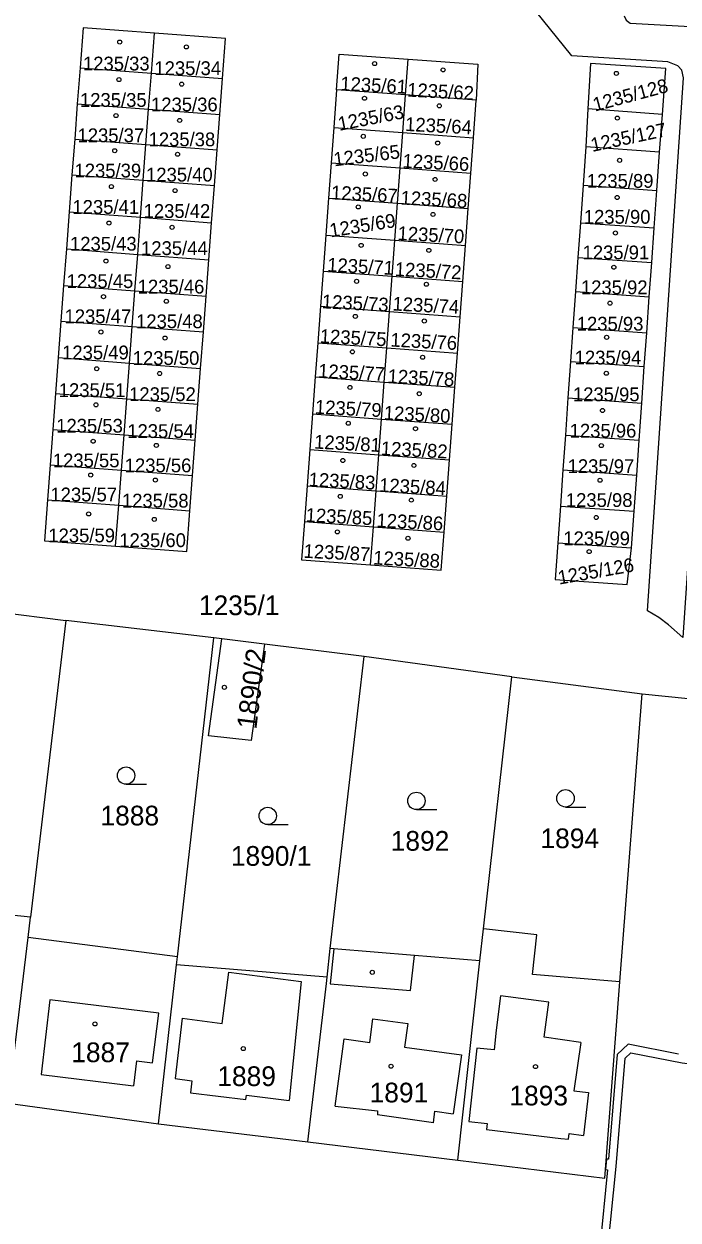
# Model space of a CAD drawing. Extents: x -869103 to -863415, y -1015889 to -1012477.
# Drawn here: x -866138.2 to -866081.7, y -1014098.2 to -1013995 of the extents above; entities that cross this region are included whole.
import ezdxf

# ---------------------------------------------------------------- set-up
doc = ezdxf.new("R2010")
doc.units = 0
for name, color, linetype in [('Hranice parcel', 7, 'Continuous'), ('Parcelní čísla', 7, 'Continuous'), ('Vnitřní kresba', 7, 'Continuous'), ('Věcná břemena k části', 7, 'Continuous'), ('Značky budov', 7, 'Continuous'), ('Značky kultur', 7, 'Continuous')]:
    doc.layers.add(name, color=color, linetype=linetype)

msp = doc.modelspace()

# ---------------------------------------------------------------- linework, layer by layer
at = {"layer": 'Hranice parcel'}
for p, q in [((-866127.17, -1013999.26), (-866126.91, -1013995.83)), ((-866105.24, -1014001.15), (-866105.01, -1013998.06)), ((-866133.32, -1013998.8), (-866133.56, -1014001.93)), ((-866133.32, -1013998.8), (-866127.17, -1013999.26)), ((-866127.41, -1014002.39), (-866127.17, -1013999.26)), ((-866127.17, -1013999.26), (-866121.03, -1013999.72)), ((-866121.27, -1014002.85), (-866121.03, -1013999.72)), ((-866111.2, -1014000.71), (-866111.44, -1014003.96)), ((-866105.24, -1014001.15), (-866111.2, -1014000.71)), ((-866105.48, -1014004.4), (-866105.24, -1014001.15)), ((-866099.15, -1014001.61), (-866105.24, -1014001.15)), ((-866099.39, -1014004.85), (-866099.15, -1014001.61)), ((-866133.56, -1014001.93), (-866133.78, -1014004.96)), ((-866133.56, -1014001.93), (-866127.41, -1014002.39)), ((-866127.64, -1014005.43), (-866127.41, -1014002.39)), ((-866127.41, -1014002.39), (-866121.27, -1014002.85)), ((-866121.5, -1014005.89), (-866121.27, -1014002.85)), ((-866089.51, -1014002.36), (-866089.7, -1014005.63)), ((-866083.08, -1014002.83), (-866089.51, -1014002.36)), ((-866083.33, -1014006.08), (-866083.08, -1014002.83)), ((-866111.44, -1014003.96), (-866111.67, -1014007)), ((-866111.44, -1014003.96), (-866105.48, -1014004.4)), ((-866105.71, -1014007.44), (-866105.48, -1014004.4)), ((-866105.48, -1014004.4), (-866099.39, -1014004.85)), ((-866099.62, -1014007.9), (-866099.39, -1014004.85)), ((-866133.78, -1014004.96), (-866134.02, -1014008.05)), ((-866133.78, -1014004.96), (-866127.64, -1014005.43)), ((-866127.87, -1014008.51), (-866127.64, -1014005.43)), ((-866127.64, -1014005.43), (-866121.5, -1014005.89)), ((-866121.73, -1014008.97), (-866121.5, -1014005.89)), ((-866089.7, -1014005.63), (-866089.93, -1014008.94)), ((-866083.33, -1014006.08), (-866089.7, -1014005.63)), ((-866083.57, -1014009.38), (-866083.33, -1014006.08)), ((-866111.67, -1014007), (-866111.89, -1014010.05)), ((-866111.67, -1014007), (-866105.71, -1014007.44)), ((-866105.93, -1014010.49), (-866105.71, -1014007.44)), ((-866105.71, -1014007.44), (-866099.62, -1014007.9)), ((-866099.84, -1014010.94), (-866099.62, -1014007.9)), ((-866134.02, -1014008.05), (-866134.26, -1014011.24)), ((-866134.02, -1014008.05), (-866127.87, -1014008.51)), ((-866128.11, -1014011.7), (-866127.87, -1014008.51)), ((-866127.87, -1014008.51), (-866121.73, -1014008.97)), ((-866121.97, -1014012.17), (-866121.73, -1014008.97)), ((-866089.93, -1014008.94), (-866090.16, -1014012.17)), ((-866089.93, -1014008.94), (-866083.57, -1014009.38)), ((-866111.89, -1014010.05), (-866112.13, -1014013.24)), ((-866111.89, -1014010.05), (-866105.93, -1014010.49)), ((-866083.79, -1014012.62), (-866083.57, -1014009.38)), ((-866106.17, -1014013.68), (-866105.93, -1014010.49)), ((-866105.93, -1014010.49), (-866099.84, -1014010.94)), ((-866100.08, -1014014.14), (-866099.84, -1014010.94)), ((-866134.26, -1014011.24), (-866134.5, -1014014.43)), ((-866134.26, -1014011.24), (-866128.11, -1014011.7)), ((-866128.35, -1014014.9), (-866128.11, -1014011.7)), ((-866128.11, -1014011.7), (-866121.97, -1014012.17)), ((-866122.21, -1014015.36), (-866121.97, -1014012.17)), ((-866090.16, -1014012.17), (-866090.37, -1014015.16)), ((-866090.16, -1014012.17), (-866083.79, -1014012.62)), ((-866084, -1014015.6), (-866083.79, -1014012.62)), ((-866112.13, -1014013.24), (-866112.36, -1014016.34)), ((-866112.13, -1014013.24), (-866106.17, -1014013.68)), ((-866106.4, -1014016.78), (-866106.17, -1014013.68)), ((-866106.17, -1014013.68), (-866100.08, -1014014.14)), ((-866100.31, -1014017.23), (-866100.08, -1014014.14)), ((-866134.5, -1014014.43), (-866134.74, -1014017.6)), ((-866134.5, -1014014.43), (-866128.35, -1014014.9)), ((-866128.59, -1014018.06), (-866128.35, -1014014.9)), ((-866128.35, -1014014.9), (-866122.21, -1014015.36)), ((-866090.37, -1014015.16), (-866090.58, -1014018.11)), ((-866090.37, -1014015.16), (-866084, -1014015.6)), ((-866122.45, -1014018.52), (-866122.21, -1014015.36)), ((-866084.21, -1014018.56), (-866084, -1014015.6)), ((-866112.36, -1014016.34), (-866112.59, -1014019.38)), ((-866112.36, -1014016.34), (-866106.4, -1014016.78)), ((-866106.63, -1014019.83), (-866106.4, -1014016.78)), ((-866106.4, -1014016.78), (-866100.31, -1014017.23)), ((-866100.54, -1014020.28), (-866100.31, -1014017.23)), ((-866134.74, -1014017.6), (-866134.97, -1014020.66)), ((-866134.74, -1014017.6), (-866128.59, -1014018.06)), ((-866128.82, -1014021.12), (-866128.59, -1014018.06)), ((-866128.59, -1014018.06), (-866122.45, -1014018.52)), ((-866090.58, -1014018.11), (-866090.8, -1014021.22)), ((-866090.58, -1014018.11), (-866084.21, -1014018.56)), ((-866122.68, -1014021.59), (-866122.45, -1014018.52)), ((-866084.43, -1014021.67), (-866084.21, -1014018.56)), ((-866112.59, -1014019.38), (-866112.82, -1014022.53)), ((-866112.59, -1014019.38), (-866106.63, -1014019.83)), ((-866106.86, -1014022.97), (-866106.63, -1014019.83)), ((-866106.63, -1014019.83), (-866100.54, -1014020.28)), ((-866100.77, -1014023.42), (-866100.54, -1014020.28)), ((-866134.97, -1014020.66), (-866135.2, -1014023.81)), ((-866134.97, -1014020.66), (-866128.82, -1014021.12)), ((-866129.06, -1014024.28), (-866128.82, -1014021.12)), ((-866128.82, -1014021.12), (-866122.68, -1014021.59)), ((-866090.8, -1014021.22), (-866091, -1014024.13)), ((-866090.8, -1014021.22), (-866084.43, -1014021.67)), ((-866122.92, -1014024.74), (-866122.68, -1014021.59)), ((-866084.64, -1014024.58), (-866084.43, -1014021.67)), ((-866112.82, -1014022.53), (-866113.04, -1014025.47)), ((-866112.82, -1014022.53), (-866106.86, -1014022.97)), ((-866107.08, -1014025.92), (-866106.86, -1014022.97)), ((-866106.86, -1014022.97), (-866100.77, -1014023.42)), ((-866100.99, -1014026.37), (-866100.77, -1014023.42)), ((-866135.2, -1014023.81), (-866135.44, -1014026.9)), ((-866135.2, -1014023.81), (-866129.06, -1014024.28)), ((-866129.29, -1014027.36), (-866129.06, -1014024.28)), ((-866129.06, -1014024.28), (-866122.92, -1014024.74)), ((-866091, -1014024.13), (-866091.23, -1014027.29)), ((-866091, -1014024.13), (-866084.64, -1014024.58)), ((-866123.15, -1014027.82), (-866122.92, -1014024.74)), ((-866113.04, -1014025.47), (-866113.28, -1014028.67)), ((-866113.04, -1014025.47), (-866107.08, -1014025.92)), ((-866084.86, -1014027.74), (-866084.64, -1014024.58)), ((-866107.32, -1014029.11), (-866107.08, -1014025.92)), ((-866107.08, -1014025.92), (-866100.99, -1014026.37)), ((-866101.23, -1014029.56), (-866100.99, -1014026.37)), ((-866135.44, -1014026.9), (-866135.67, -1014030.01)), ((-866135.44, -1014026.9), (-866129.29, -1014027.36)), ((-866129.52, -1014030.48), (-866129.29, -1014027.36)), ((-866129.29, -1014027.36), (-866123.15, -1014027.82)), ((-866091.23, -1014027.29), (-866091.45, -1014030.5)), ((-866091.23, -1014027.29), (-866084.86, -1014027.74)), ((-866123.39, -1014030.94), (-866123.15, -1014027.82)), ((-866085.09, -1014030.94), (-866084.86, -1014027.74)), ((-866113.28, -1014028.67), (-866113.51, -1014031.73)), ((-866113.28, -1014028.67), (-866107.32, -1014029.11)), ((-866107.55, -1014032.18), (-866107.32, -1014029.11)), ((-866107.32, -1014029.11), (-866101.23, -1014029.56)), ((-866101.46, -1014032.63), (-866101.23, -1014029.56)), ((-866135.67, -1014030.01), (-866135.9, -1014033.07)), ((-866135.67, -1014030.01), (-866129.52, -1014030.48)), ((-866129.75, -1014033.53), (-866129.52, -1014030.48)), ((-866129.52, -1014030.48), (-866123.39, -1014030.94)), ((-866091.45, -1014030.5), (-866091.66, -1014033.5)), ((-866091.45, -1014030.5), (-866085.09, -1014030.94)), ((-866123.62, -1014033.99), (-866123.39, -1014030.94)), ((-866113.51, -1014031.73), (-866113.74, -1014034.86)), ((-866113.51, -1014031.73), (-866107.55, -1014032.18)), ((-866085.3, -1014033.95), (-866085.09, -1014030.94)), ((-866107.78, -1014035.3), (-866107.55, -1014032.18)), ((-866107.55, -1014032.18), (-866101.46, -1014032.63)), ((-866101.69, -1014035.75), (-866101.46, -1014032.63)), ((-866135.9, -1014033.07), (-866136.13, -1014036.08)), ((-866135.9, -1014033.07), (-866129.75, -1014033.53)), ((-866129.98, -1014036.54), (-866129.75, -1014033.53)), ((-866129.75, -1014033.53), (-866123.62, -1014033.99)), ((-866091.66, -1014033.5), (-866091.88, -1014036.61)), ((-866091.66, -1014033.5), (-866085.3, -1014033.95)), ((-866123.84, -1014037.01), (-866123.62, -1014033.99)), ((-866085.52, -1014037.06), (-866085.3, -1014033.95)), ((-866113.74, -1014034.86), (-866113.97, -1014037.95)), ((-866113.74, -1014034.86), (-866107.78, -1014035.3)), ((-866108.01, -1014038.4), (-866107.78, -1014035.3)), ((-866107.78, -1014035.3), (-866101.69, -1014035.75)), ((-866101.92, -1014038.85), (-866101.69, -1014035.75)), ((-866136.13, -1014036.08), (-866129.98, -1014036.54)), ((-866130.25, -1014040.06), (-866129.98, -1014036.54)), ((-866129.98, -1014036.54), (-866123.84, -1014037.01)), ((-866091.88, -1014036.61), (-866092.11, -1014039.77)), ((-866091.88, -1014036.61), (-866085.52, -1014037.06)), ((-866085.74, -1014040.22), (-866085.52, -1014037.06)), ((-866113.97, -1014037.95), (-866108.01, -1014038.4)), ((-866108.25, -1014041.69), (-866108.01, -1014038.4)), ((-866108.01, -1014038.4), (-866101.92, -1014038.85)), ((-866092.11, -1014039.77), (-866092.34, -1014042.96)), ((-866092.11, -1014039.77), (-866085.74, -1014040.22)), ((-866086.11, -1014043.37), (-866085.74, -1014040.22)), ((-866092.34, -1014042.96), (-866086.11, -1014043.37)), ((-866143.47, -1014045.35), (-866134.54, -1014046.47)), ((-866134.54, -1014046.47), (-866137.59, -1014072.06)), ((-866121.77, -1014047.97), (-866134.54, -1014046.47)), ((-866124.91, -1014075.5), (-866121.77, -1014047.97)), ((-866121.08, -1014048.06), (-866121.77, -1014047.97)), ((-866117.42, -1014048.52), (-866121.08, -1014048.06)), ((-866108.81, -1014049.6), (-866117.42, -1014048.52)), ((-866111.73, -1014074.78), (-866108.81, -1014049.6)), ((-866096.08, -1014051.33), (-866108.81, -1014049.6)), ((-866098.51, -1014073.07), (-866096.08, -1014051.33)), ((-866096.08, -1014051.33), (-866084.83, -1014052.8)), ((-866086.74, -1014077.65), (-866084.83, -1014052.8)), ((-866084.83, -1014052.8), (-866080.86, -1014053.22)), ((-866137.81, -1014073.84), (-866137.59, -1014072.06)), ((-866139.51, -1014088.11), (-866137.81, -1014073.84)), ((-866124.91, -1014075.5), (-866137.81, -1014073.84)), ((-866098.82, -1014075.85), (-866098.51, -1014073.07)), ((-866112.01, -1014077.26), (-866111.73, -1014074.78)), ((-866124.99, -1014076.19), (-866124.91, -1014075.5)), ((-866100.73, -1014093.02), (-866098.82, -1014075.85)), ((-866126.55, -1014089.91), (-866124.99, -1014076.19)), ((-866112.01, -1014077.26), (-866124.99, -1014076.19)), ((-866088.04, -1014094.59), (-866086.74, -1014077.65)), ((-866139.51, -1014088.11), (-866126.55, -1014089.91)), ((-866126.55, -1014089.91), (-866113.66, -1014091.46)), ((-866113.66, -1014091.46), (-866100.73, -1014093.02)), ((-866100.73, -1014093.02), (-866088.04, -1014094.59))]:
    msp.add_line(p, q, dxfattribs=at)
for points in [[(-866086.37, -1013994.34), (-866086.2, -1013994.7), (-866085.86, -1013994.95), (-866080.16, -1013995.28), (-866079.34, -1013995.84), (-866078.76, -1013996.61), (-866078.28, -1013997.55), (-866078.04, -1013998.64), (-866078.04, -1013999.43), (-866081.32, -1014047.95), (-866082.54, -1014046.85), (-866083.4, -1014046.21), (-866084.37, -1014045.66), (-866081.25, -1013999.67), (-866081.41, -1013999.02), (-866081.75, -1013998.65), (-866082.62, -1013998.29), (-866090.88, -1013997.79), (-866094.03, -1013993.9)], [(-866126.91, -1013995.83), (-866133.06, -1013995.36), (-866133.32, -1013998.8)], [(-866121.03, -1013999.72), (-866120.78, -1013996.29), (-866126.91, -1013995.83)], [(-866111.2, -1014000.71), (-866110.97, -1013997.62), (-866105.01, -1013998.06)], [(-866105.01, -1013998.06), (-866098.99, -1013998.49), (-866099.15, -1014001.61)], [(-866083.08, -1014002.83), (-866082.78, -1013998.86), (-866089.28, -1013998.45), (-866089.51, -1014002.36)], [(-866136.13, -1014036.08), (-866136.39, -1014039.6), (-866130.25, -1014040.06)], [(-866130.25, -1014040.06), (-866124.11, -1014040.53), (-866123.84, -1014037.01)], [(-866113.97, -1014037.95), (-866114.21, -1014041.25), (-866108.25, -1014041.69)], [(-866108.25, -1014041.69), (-866102.16, -1014042.14), (-866101.92, -1014038.85)], [(-866117.42, -1014048.52), (-866118.55, -1014056.84), (-866122.23, -1014056.42), (-866121.08, -1014048.06)], [(-866137.59, -1014072.06), (-866147.31, -1014071.06), (-866146.81, -1014066.96), (-866150.13, -1014066.47)], [(-866086.74, -1014077.65), (-866094.28, -1014077.02), (-866093.9, -1014073.61), (-866098.51, -1014073.07)], [(-866098.82, -1014075.85), (-866104.48, -1014075.38), (-866111.43, -1014074.8), (-866111.73, -1014074.78)], [(-866113.66, -1014091.46), (-866112.07, -1014077.78), (-866112.01, -1014077.26)]]:
    msp.add_lwpolyline(points, dxfattribs=at)
at = {"layer": 'Vnitřní kresba'}
for p, q in [((-866111.43, -1014074.8), (-866111.75, -1014077.81)), ((-866104.82, -1014078.39), (-866104.48, -1014075.38)), ((-866121.06, -1014081.23), (-866120.48, -1014076.83)), ((-866120.48, -1014076.83), (-866114.25, -1014077.63)), ((-866114.25, -1014077.63), (-866115.27, -1014087.88)), ((-866111.75, -1014077.81), (-866104.82, -1014078.39)), ((-866135.93, -1014079.19), (-866136.68, -1014085.63)), ((-866126.52, -1014080.35), (-866135.93, -1014079.19)), ((-866127.08, -1014084.63), (-866126.52, -1014080.35)), ((-866124.5, -1014080.78), (-866125.13, -1014086)), ((-866124.5, -1014080.78), (-866121.06, -1014081.23)), ((-866108.32, -1014082.88), (-866108.05, -1014080.85)), ((-866108.05, -1014080.85), (-866105.05, -1014081.24)), ((-866105.05, -1014081.24), (-866105.33, -1014083.29)), ((-866111.32, -1014088.37), (-866110.55, -1014082.58)), ((-866110.55, -1014082.58), (-866108.32, -1014082.88)), ((-866105.33, -1014083.29), (-866100.42, -1014083.96)), ((-866090.12, -1014082.89), (-866090.73, -1014087.06)), ((-866100.42, -1014083.96), (-866101.13, -1014089.04)), ((-866128.45, -1014084.46), (-866128.72, -1014086.61)), ((-866128.45, -1014084.46), (-866127.08, -1014084.63)), ((-866136.68, -1014085.63), (-866128.72, -1014086.61)), ((-866125.13, -1014086), (-866123.68, -1014086.18)), ((-866123.68, -1014086.18), (-866123.8, -1014087.22)), ((-866123.8, -1014087.22), (-866119.02, -1014087.79)), ((-866119.02, -1014087.79), (-866118.97, -1014087.42)), ((-866118.97, -1014087.42), (-866115.27, -1014087.88)), ((-866090.73, -1014087.06), (-866089.45, -1014087.21)), ((-866089.45, -1014087.21), (-866089.88, -1014090.91)), ((-866111.32, -1014088.37), (-866107.65, -1014088.79)), ((-866107.65, -1014088.79), (-866107.67, -1014089.11)), ((-866102.84, -1014089.82), (-866107.67, -1014089.11)), ((-866102.84, -1014089.82), (-866102.7, -1014088.82)), ((-866102.7, -1014088.82), (-866101.13, -1014089.04)), ((-866098.26, -1014090.38), (-866091.83, -1014091.17)), ((-866091.83, -1014091.17), (-866091.17, -1014091.23)), ((-866091.17, -1014091.23), (-866091.11, -1014090.73)), ((-866091.11, -1014090.73), (-866089.88, -1014090.91))]:
    msp.add_line(p, q, dxfattribs=at)
msp.add_lwpolyline([(-866090.12, -1014082.89), (-866093.27, -1014082.42), (-866092.88, -1014079.39), (-866097.06, -1014078.87), (-866097.42, -1014081.81), (-866097.6, -1014083.52), (-866099.09, -1014083.36), (-866099.77, -1014089.7), (-866098.2, -1014089.86), (-866098.26, -1014090.38)], dxfattribs=at)
at = {"layer": 'Věcná břemena k části'}
for points in [[(-866081.68, -1014083.88), (-866086.03, -1014083.02), (-866086.98, -1014083.91), (-866087.72, -1014092.96), (-866087.91, -1014092.95), (-866087.98, -1014093.85), (-866087.81, -1014093.87), (-866088.47, -1014100.6)], [(-866138.85, -1014099.9), (-866126.98, -1014101.57), (-866123.49, -1014101.89), (-866116.37, -1014102.66), (-866092.66, -1014105.81), (-866088.56, -1014106.7), (-866088.26, -1014107.08), (-866088.42, -1014110.08), (-866088.97, -1014110.12), (-866089.05, -1014110.81), (-866088.22, -1014110.98), (-866087.64, -1014110.46), (-866087.46, -1014106.98), (-866087.55, -1014106.39), (-866088.27, -1014105.23), (-866087.8, -1014100.67), (-866087.07, -1014093.57), (-866086.3, -1014084.23), (-866085.81, -1014083.78), (-866081.38, -1014084.65), (-866080.66, -1014084.71), (-866079.96, -1014085.92), (-866069.98, -1014091.74), (-866051.77, -1014100.07)]]:
    msp.add_lwpolyline(points, dxfattribs=at)
at = {"layer": 'Značky budov'}
for centre in [(-866129.9, -1013996.59), (-866124.15, -1013997.01), (-866107.91, -1013998.45), (-866129.97, -1013999.83), (-866102, -1013998.99), (-866087.05, -1013999.29), (-866124.55, -1014000.22), (-866108.78, -1014001.44), (-866130.22, -1014002.93), (-866102.33, -1014002.09), (-866124.73, -1014003.35), (-866086.96, -1014003.15), (-866108.89, -1014004.72), (-866130.33, -1014005.96), (-866102.47, -1014005.3), (-866124.91, -1014006.27), (-866086.77, -1014006.79), (-866108.71, -1014007.97), (-866130.62, -1014009.06), (-866102.69, -1014008.44), (-866125.12, -1014009.4), (-866086.98, -1014010), (-866109.32, -1014010.81), (-866130.83, -1014012.2), (-866102.87, -1014011.46), (-866125.38, -1014012.57), (-866087.13, -1014013.06), (-866109.07, -1014014.13), (-866103.23, -1014014.56), (-866131.09, -1014015.48), (-866125.74, -1014015.96), (-866087.27, -1014016.01), (-866109.46, -1014017.23), (-866103.44, -1014017.48), (-866131.3, -1014018.55), (-866125.88, -1014018.95), (-866087.6, -1014019.11), (-866109.57, -1014020.25), (-866131.52, -1014021.6), (-866103.62, -1014020.65), (-866125.99, -1014022.12), (-866087.89, -1014022.06), (-866109.82, -1014023.31), (-866103.77, -1014023.78), (-866131.88, -1014024.77), (-866126.46, -1014025.18), (-866087.92, -1014025.16), (-866110.04, -1014026.38), (-866104.06, -1014026.92), (-866131.95, -1014027.88), (-866126.6, -1014028.28), (-866088.25, -1014028.37), (-866110.18, -1014029.47), (-866104.38, -1014029.94), (-866132.19, -1014031.02), (-866126.74, -1014031.38), (-866088.35, -1014031.4), (-866110.65, -1014032.68), (-866132.4, -1014033.94), (-866104.52, -1014033.11), (-866126.82, -1014034.37), (-866088.46, -1014034.39), (-866110.87, -1014035.78), (-866104.74, -1014036.1), (-866132.58, -1014037.29), (-866126.92, -1014037.76), (-866088.79, -1014037.6), (-866111.12, -1014038.84), (-866105.03, -1014039.39), (-866089.4, -1014040.54), (-866120.87, -1014052.25), (-866108.11, -1014076.83), (-866132.04, -1014081.28), (-866119.24, -1014083.41), (-866106.49, -1014084.93), (-866094.03, -1014084.96)]:
    msp.add_circle(centre, 0.175, dxfattribs=at)
at = {"layer": 'Značky kultur'}
for p, q in [((-866129.35, -1014060.61), (-866127.6, -1014060.61)), ((-866091.44, -1014062.57), (-866089.69, -1014062.57)), ((-866104.3, -1014062.79), (-866102.55, -1014062.79)), ((-866117.13, -1014064.09), (-866115.38, -1014064.09))]:
    msp.add_line(p, q, dxfattribs=at)
for centre in [(-866129.35, -1014059.86), (-866104.3, -1014062.04), (-866091.44, -1014061.82), (-866117.13, -1014063.34)]:
    msp.add_circle(centre, 0.75, dxfattribs=at)

# ---------------------------------------------------------------- texts
at = {"layer": 'Parcelní čísla'}
for s, height, p in [('1235/33', 1.19, (-866133.07, -1013999.04)), ('1235/34', 1.19, (-866126.91, -1013999.44)), ('1235/35', 1.19, (-866133.33, -1014002.18)), ('1235/36', 1.19, (-866127.2, -1014002.57)), ('1235/37', 1.19, (-866133.54, -1014005.23)), ('1235/38', 1.19, (-866127.41, -1014005.58)), ('1235/39', 1.19, (-866133.8, -1014008.27)), ('1235/40', 1.19, (-866127.63, -1014008.62)), ('1235/89', 1.19, (-866089.6, -1014009.16)), ('1235/41', 1.19, (-866133.98, -1014011.41)), ('1235/42', 1.19, (-866127.84, -1014011.76)), ('1235/90', 1.19, (-866089.86, -1014012.26)), ('1235/43', 1.19, (-866134.19, -1014014.58)), ('1235/44', 1.19, (-866128.06, -1014014.96)), ('1235/91', 1.19, (-866089.97, -1014015.33)), ('1235/45', 1.19, (-866134.48, -1014017.81)), ('1235/46', 1.19, (-866128.35, -1014018.28)), ('1235/92', 1.19, (-866090.11, -1014018.34)), ('1235/47', 1.19, (-866134.66, -1014020.84)), ('1235/48', 1.19, (-866128.49, -1014021.27)), ('1235/93', 1.19, (-866090.47, -1014021.48)), ('1235/49', 1.19, (-866134.87, -1014023.96)), ('1235/50', 1.19, (-866128.78, -1014024.44)), ('1235/94', 1.19, (-866090.65, -1014024.4)), ('1235/51', 1.19, (-866135.16, -1014027.21)), ('1235/52', 1.19, (-866129.09, -1014027.56)), ('1235/95', 1.19, (-866090.8, -1014027.57)), ('1235/53', 1.19, (-866135.38, -1014030.28)), ('1235/54', 1.19, (-866129.25, -1014030.74)), ('1235/96', 1.19, (-866091.08, -1014030.71)), ('1235/55', 1.19, (-866135.67, -1014033.27)), ('1235/56', 1.19, (-866129.47, -1014033.7)), ('1235/97', 1.19, (-866091.26, -1014033.77)), ('1235/57', 1.19, (-866135.88, -1014036.21)), ('1235/58', 1.19, (-866129.71, -1014036.74)), ('1235/98', 1.19, (-866091.41, -1014036.69)), ('1235/59', 1.19, (-866136.06, -1014039.74)), ('1235/60', 1.19, (-866129.94, -1014040.15)), ('1235/99', 1.19, (-866091.63, -1014039.99)), ('1235/1', 1.7, (-866123.07, -1014046.02)), ('1888', 1.7, (-866131.56, -1014064.16)), ('1892', 1.7, (-866106.52, -1014066.34)), ('1894', 1.7, (-866093.6, -1014066.12)), ('1890/1', 1.7, (-866120.31, -1014067.64)), ('1887', 1.7, (-866134.08, -1014084.58)), ('1889', 1.7, (-866121.48, -1014086.64)), ('1891', 1.7, (-866108.34, -1014088.05)), ('1893', 1.7, (-866096.28, -1014088.31))]:
    msp.add_text(s, height=height, dxfattribs=at).set_placement(p)
for s, height, rotation, p in [('1235/61', 1.19, 357, (-866110.89, -1014000.75)), ('1235/62', 1.19, 357, (-866105.12, -1014001.29)), ('1235/128', 1.19, 15, (-866088.9, -1014002.59)), ('1235/63', 1.19, 11, (-866110.95, -1014004.25)), ('1235/64', 1.19, 357, (-866105.3, -1014004.25)), ('1235/127', 1.19, 12, (-866089.13, -1014006.07)), ('1235/65', 1.19, 7, (-866111.38, -1014007.31)), ('1235/66', 1.19, 357, (-866105.52, -1014007.42)), ('1235/67', 1.19, 357, (-866111.69, -1014010.15)), ('1235/68', 1.19, 357, (-866105.69, -1014010.6)), ('1235/69', 1.19, 9, (-866111.7, -1014013.44)), ('1235/70', 1.19, 357, (-866105.95, -1014013.66)), ('1235/71', 1.19, 357, (-866112.02, -1014016.38)), ('1235/72', 1.19, 357, (-866106.19, -1014016.76)), ('1235/73', 1.19, 357, (-866112.48, -1014019.55)), ('1235/74', 1.19, 357, (-866106.39, -1014019.74)), ('1235/75', 1.19, 357, (-866112.66, -1014022.53)), ('1235/76', 1.19, 357, (-866106.57, -1014022.85)), ('1235/77', 1.19, 357, (-866112.8, -1014025.53)), ('1235/78', 1.19, 357, (-866106.81, -1014025.99)), ('1235/79', 1.19, 357, (-866113.08, -1014028.64)), ('1235/80', 1.19, 357, (-866107.14, -1014029.15)), ('1235/81', 1.19, 357, (-866113.15, -1014031.65)), ('1235/82', 1.19, 357, (-866107.39, -1014032.21)), ('1235/83', 1.19, 357, (-866113.62, -1014034.9)), ('1235/84', 1.19, 357, (-866107.54, -1014035.38)), ('1235/85', 1.19, 357, (-866113.88, -1014037.96)), ('1235/86', 1.19, 357, (-866107.77, -1014038.42)), ('1235/87', 1.19, 357, (-866114.06, -1014041.07)), ('1235/88', 1.19, 357, (-866108.05, -1014041.65)), ('1235/126', 1.19, 10, (-866091.99, -1014043.39)), ('1890/2', 1.7, 83, (-866118.12, -1014055.92))]:
    msp.add_text(s, height=height, rotation=rotation, dxfattribs=at).set_placement(p)

doc.saveas('drawing.dxf')
